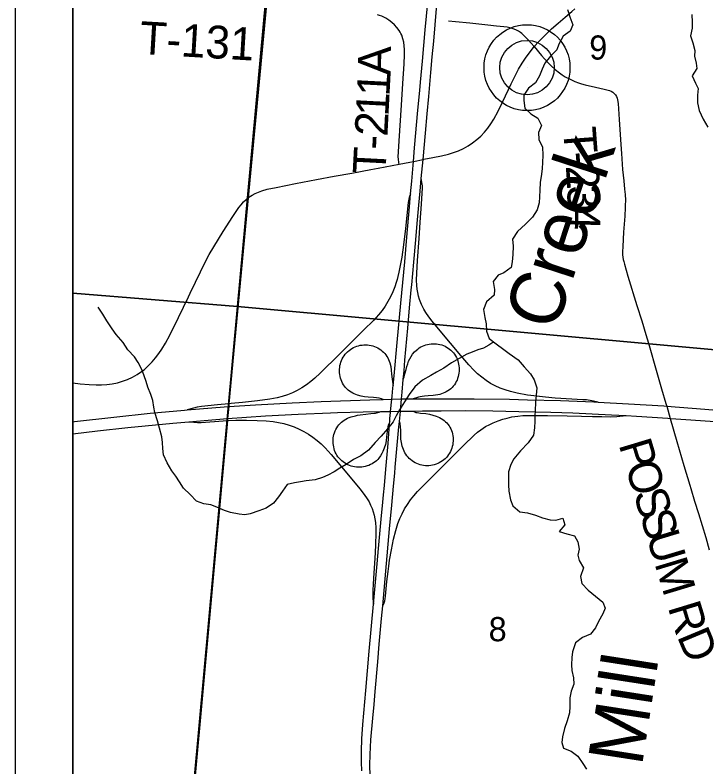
# Model space of a CAD drawing. Extents: x -209 to 4852, y 0 to 905.
# Drawn here: x 57.34 to 81.27, y 222.94 to 248.99 of the extents above; entities that cross this region are included whole.
import ezdxf

# ---------------------------------------------------------------- set-up
doc = ezdxf.new("R2010")
doc.units = 0
for name, color, linetype in [('Default', 7, 'Continuous'), ('GM_X_Corporation', 7, 'Continuous'), ('GM_X_County_Road', 7, 'Continuous'), ('GM_X_County_Road_Text', 7, 'Continuous'), ('GM_X_County_ROW', 7, 'Continuous'), ('GM_X_County_Subdivision', 7, 'Continuous'), ('GM_X_Minor_Lake_Text', 7, 'Continuous'), ('GM_X_Minor_River', 7, 'Continuous'), ('GM_X_Rail_Line', 7, 'Continuous'), ('GM_X_Rail_Line_Text', 7, 'Continuous'), ('GM_X_Section_Text', 7, 'Continuous'), ('GM_X_Township_Road', 7, 'Continuous'), ('GM_X_Township_Road_Text', 7, 'Continuous'), ('GM_X_Township_Subdivision_Text', 7, 'Continuous'), ('SH_Data', 7, 'Continuous')]:
    doc.layers.add(name, color=color, linetype=linetype)

msp = doc.modelspace()

# ---------------------------------------------------------------- linework, layer by layer
at = {"layer": 'Default'}
for points in [[(59.342, 338.559), (195.342, 338.559), (195.342, 202.559), (59.342, 202.559)], [(195.342, 202.559), (195.342, 338.559), (59.342, 338.559), (59.342, 202.559)]]:
    msp.add_lwpolyline(points, close=True, dxfattribs=at)
at = {"layer": 'GM_X_Corporation'}
for points in [[(71.004, 238.842), (71.062, 239.471), (71.078, 239.639), (71.147, 240.425), (71.219, 241.207), (71.269, 241.773), (71.328, 242.408), (71.371, 242.891), (71.411, 243.325), (71.473, 243.989), (71.558, 244.897), (71.614, 245.567), (71.667, 246.166), (71.742, 247.001), (71.792, 247.547), (71.841, 248.083), (71.939, 249.211), (71.966, 249.513), (71.986, 249.75), (72.041, 250.391), (72.091, 250.894), (72.203, 252.114), (72.245, 252.601), (72.295, 253.174)], [(69.35, 222.805), (69.339, 223.114), (69.34, 223.486), (69.355, 223.92), (69.386, 224.415), (69.488, 225.591), (69.611, 226.951), (69.757, 228.587), (69.881, 229.981), (69.927, 230.511), (70.023, 231.531), (70.082, 232.119), (70.103, 232.372), (70.131, 232.695), (70.184, 233.263), (70.259, 234.145), (70.309, 234.825), (70.316, 234.904), (70.325, 235.013), (70.343, 235.217), (70.348, 235.26), (70.39, 235.681), (70.401, 235.789), (70.423, 236.061), (70.434, 236.156), (70.473, 236.492), (70.575, 237.65), (70.7, 239.008), (70.835, 240.445), (70.907, 241.299), (70.999, 242.345), (71.039, 242.801), (71.078, 243.239), (71.131, 243.795), (71.141, 243.922), (71.179, 244.391), (71.294, 245.69), (71.357, 246.376), (71.384, 246.662), (71.453, 247.389), (71.547, 248.473), (71.712, 250.266)], [(70.686, 235.251), (70.687, 235.265), (70.729, 235.691), (70.752, 235.927), (70.788, 236.37), (70.812, 236.663), (70.838, 237.038), (70.94, 238.143), (71.004, 238.842)], [(69.773, 225.108), (69.809, 225.559), (69.901, 226.585), (69.954, 227.194), (70.036, 228.091), (70.075, 228.528), (70.312, 231.195), (70.387, 232.014), (70.447, 232.668), (70.489, 233.116), (70.509, 233.332), (70.634, 234.73), (70.652, 234.911), (70.686, 235.251)], [(71.045, 218.165), (71.025, 218.234), (71.012, 218.276), (70.97, 218.359), (70.735, 218.729), (70.586, 219.002), (70.449, 219.282), (70.323, 219.567), (70.207, 219.856), (70.072, 220.213), (70.009, 220.394), (69.947, 220.611), (69.888, 220.821), (69.829, 221.061), (69.763, 221.407), (69.71, 221.719), (69.671, 222.041), (69.648, 222.34), (69.635, 222.643), (69.625, 223.005), (69.635, 223.379), (69.664, 223.886), (69.735, 224.639), (69.773, 225.108)]]:
    msp.add_lwpolyline(points, dxfattribs=at)
at = {"layer": 'GM_X_County_Road'}
for points in [[(76.478, 249.178), (76.559, 248.928), (76.663, 248.646), (76.563, 248.435), (76.327, 248.254), (76.174, 247.983), (76.104, 247.786), (75.89, 247.56), (75.692, 247.319), (75.6, 247.115), (75.507, 246.888), (75.362, 246.646), (75.126, 246.458), (74.957, 246.217), (74.956, 246.028), (74.999, 245.769), (75.202, 245.563), (75.451, 245.417), (75.57, 245.166), (75.47, 244.924), (75.483, 244.674), (75.602, 244.415), (75.615, 244.135), (75.613, 243.884), (75.597, 243.672), (75.572, 243.475), (75.532, 243.195), (75.515, 242.922), (75.506, 242.687), (75.489, 242.482), (75.427, 242.24), (75.259, 241.984), (75.022, 241.75), (74.74, 241.487), (74.572, 241.223)], [(80.774, 249.01), (80.787, 248.745), (80.785, 248.54), (80.738, 248.267), (80.812, 248.024), (80.878, 247.766), (80.869, 247.569), (80.928, 247.326), (80.949, 247.136), (80.796, 246.887), (80.907, 246.636), (81.004, 246.446), (80.972, 246.211), (80.97, 245.945), (81.036, 245.687), (81.17, 245.383), (81.335, 245.109)], [(74.572, 241.223), (74.593, 240.988), (74.576, 240.692), (74.559, 240.442), (74.527, 240.245), (74.268, 240.057), (74.078, 239.975), (73.903, 239.764), (73.946, 239.484), (73.937, 239.286), (73.663, 239.053), (73.563, 238.789), (73.613, 238.508), (73.657, 238.295), (73.663, 238.045), (73.759, 237.786), (74.008, 237.603), (74.263, 237.404), (74.459, 237.266), (74.76, 237.051), (74.97, 236.807), (75.188, 236.563), (75.322, 236.357), (75.411, 236.076), (75.394, 235.818), (75.362, 235.568), (75.352, 235.295), (75.343, 235.106), (75.342, 234.916), (75.333, 234.696), (75.3, 234.431), (75.109, 234.175), (74.842, 233.889), (74.613, 233.617), (74.506, 233.421), (74.436, 233.171), (74.427, 232.906), (74.433, 232.716), (74.446, 232.496), (74.504, 232.2), (74.586, 231.987), (74.827, 231.781), (75.084, 231.748), (75.363, 231.663), (75.612, 231.57), (75.869, 231.508), (76.065, 231.491), (76.316, 231.565), (76.382, 231.329), (76.183, 231.103), (76.455, 231.018), (76.712, 230.948), (76.831, 230.742), (76.882, 230.484), (76.836, 230.28), (76.879, 230.09), (77.029, 229.838), (76.928, 229.543), (76.964, 229.301), (77.19, 229.071), (77.445, 228.857), (77.701, 228.651), (77.783, 228.445), (77.698, 228.249), (77.545, 227.985), (77.445, 227.758), (77.269, 227.547), (76.996, 227.427), (76.752, 227.24), (76.652, 226.93), (76.62, 226.733), (76.61, 226.482), (76.624, 226.285), (76.683, 226.027), (76.689, 225.807), (76.604, 225.573), (76.556, 225.338), (76.554, 225.042), (76.545, 224.822), (76.467, 224.542), (76.367, 224.278), (76.297, 223.99), (76.273, 223.793), (76.332, 223.596), (76.603, 223.487), (76.829, 223.319), (77.001, 223.067), (77.136, 222.869)], [(73.922, 237.666), (73.75, 237.551), (73.56, 237.447), (73.371, 237.387), (73.173, 237.313), (72.984, 237.246), (72.718, 237.089), (72.452, 236.947), (72.193, 236.759), (71.942, 236.617), (71.737, 236.505), (71.456, 236.347), (71.19, 236.114), (70.991, 235.85), (70.83, 235.586), (70.654, 235.315), (70.539, 235.103), (70.439, 234.899), (70.241, 234.658), (70.019, 234.402), (69.813, 234.183), (69.584, 233.912), (69.318, 233.717), (69.067, 233.59), (68.809, 233.425), (68.589, 233.29), (68.391, 233.163), (68.178, 233.05), (67.988, 232.968), (67.731, 232.887), (67.428, 232.851), (67.223, 232.822), (67.019, 232.786), (66.769, 232.727), (66.6, 232.493), (66.47, 232.297), (66.287, 232.079), (66.036, 231.906), (65.786, 231.817), (65.49, 231.713), (65.301, 231.676), (65.104, 231.701), (64.802, 231.756), (64.598, 231.826), (64.334, 231.941), (64.123, 232.019), (63.881, 232.058), (63.624, 232.151), (63.407, 232.38), (63.174, 232.602), (63.039, 232.815), (62.912, 233.013), (62.777, 233.204), (62.605, 233.478), (62.486, 233.752), (62.458, 233.972), (62.444, 234.184), (62.423, 234.374), (62.35, 234.678), (62.276, 234.936), (62.187, 235.218), (62.151, 235.407), (62.115, 235.635), (62.041, 235.84), (61.937, 236.099), (61.885, 236.297), (61.818, 236.487), (61.729, 236.715), (61.61, 236.958), (61.483, 237.149), (61.243, 237.393), (61.086, 237.645), (60.846, 237.919), (60.703, 238.117), (60.524, 238.392), (60.382, 238.628), (60.217, 238.872)]]:
    msp.add_lwpolyline(points, dxfattribs=at)
at = {"layer": 'GM_X_County_Road_Text'}
for points in [[(75.323, 247.898), (75.482, 248.074), (75.655, 248.251), (75.923, 248.508), (76.155, 248.714), (76.389, 248.917), (76.626, 249.117), (76.728, 249.204)], [(70.641, 243.825), (70.833, 243.861), (71.016, 243.897), (71.141, 243.922), (71.473, 243.989), (71.503, 243.995), (71.808, 244.053), (72.112, 244.113), (72.352, 244.173), (72.53, 244.227), (72.703, 244.291), (72.872, 244.367), (73.034, 244.456), (73.187, 244.559), (73.332, 244.674), (73.469, 244.799), (73.596, 244.933), (73.714, 245.076), (73.822, 245.226), (73.92, 245.384), (74.067, 245.656), (74.23, 245.991), (74.519, 246.611), (74.66, 246.889), (74.779, 247.112), (74.905, 247.321), (75.041, 247.531), (75.191, 247.731), (75.323, 247.898)], [(69.658, 243.641), (69.918, 243.69), (70.641, 243.825)], [(65.413, 242.656), (65.444, 242.682), (65.55, 242.75), (65.661, 242.809), (65.776, 242.86), (65.894, 242.903), (66.075, 242.953), (66.379, 243.019), (67.049, 243.152), (67.782, 243.291), (68.392, 243.408), (69.003, 243.517), (69.658, 243.641)], [(63.346, 239.23), (63.405, 239.353), (63.951, 240.47), (64.067, 240.69), (64.224, 240.959), (64.552, 241.487), (64.888, 242.011), (65.097, 242.32), (65.173, 242.42), (65.256, 242.514), (65.346, 242.603), (65.411, 242.655), (65.413, 242.656)], [(59.342, 236.251), (59.599, 236.217), (59.907, 236.187), (60.155, 236.175), (60.34, 236.177), (60.525, 236.189), (60.708, 236.214), (60.889, 236.253), (61.067, 236.305), (61.24, 236.37), (61.407, 236.449), (61.569, 236.539), (61.723, 236.642), (61.82, 236.717), (61.957, 236.842), (62.086, 236.974), (62.208, 237.114), (62.32, 237.261), (62.425, 237.415), (62.553, 237.626), (62.697, 237.9), (63.001, 238.513), (63.346, 239.23)]]:
    msp.add_lwpolyline(points, dxfattribs=at)
at = {"layer": 'GM_X_County_ROW'}
for points in [[(70.641, 243.825), (70.636, 243.868), (70.618, 244.012), (70.614, 244.07), (70.647, 244.628), (70.729, 245.869), (70.774, 246.614), (70.82, 247.297), (70.834, 247.608), (70.832, 247.796), (70.822, 247.921), (70.802, 248.046), (70.772, 248.168), (70.731, 248.288), (70.706, 248.346), (70.677, 248.402), (70.644, 248.456), (70.569, 248.558), (70.484, 248.652), (70.39, 248.736), (70.29, 248.813), (70.183, 248.879), (70.108, 248.92), (70.04, 248.949), (69.964, 248.976), (69.899, 248.995)], [(75.323, 247.898), (75.107, 248.126), (74.983, 248.263), (74.893, 248.349), (74.846, 248.388), (74.778, 248.435), (74.686, 248.482), (74.593, 248.515), (74.481, 248.544), (74.387, 248.565), (74.264, 248.585), (74.018, 248.61), (73.71, 248.645), (73.093, 248.703), (72.6, 248.755), (72.353, 248.774)], [(75.323, 247.898), (75.576, 247.594), (75.782, 247.362), (75.91, 247.228), (76.046, 247.102), (76.191, 246.987), (76.292, 246.916), (76.397, 246.852), (76.561, 246.766), (76.731, 246.691), (76.851, 246.647), (76.962, 246.611), (77.082, 246.576), (77.445, 246.495), (77.746, 246.422), (77.925, 246.372), (77.985, 246.349), (78.041, 246.318), (78.094, 246.275), (78.135, 246.228), (78.168, 246.172), (78.192, 246.112), (78.207, 246.05), (78.224, 245.924), (78.263, 245.366), (78.321, 244.501), (78.34, 244.191), (78.382, 243.634), (78.4, 243.441), (78.419, 243.244), (78.453, 242.955), (78.469, 242.768), (78.477, 242.581), (78.476, 242.394), (78.471, 242.269), (78.464, 242.083), (78.461, 242.02), (78.413, 241.463), (78.384, 240.968), (78.379, 240.783), (78.383, 240.679), (78.389, 240.607), (78.405, 240.518), (78.42, 240.456), (78.444, 240.359), (78.566, 239.942), (78.876, 238.932), (79.042, 238.397), (79.185, 237.921), (79.273, 237.623), (79.566, 236.608), (79.731, 236.044)], [(79.731, 236.044), (79.881, 235.535), (79.908, 235.443), (80.03, 235.019), (80.26, 234.22), (80.505, 233.386), (80.708, 232.699), (80.74, 232.593)], [(80.74, 232.593), (80.875, 232.146), (81.007, 231.718), (81.259, 230.886), (81.383, 230.469)]]:
    msp.add_lwpolyline(points, dxfattribs=at)
at = {"layer": 'GM_X_County_Subdivision'}
msp.add_line((75.071, 247.168), (75.071, 247.168), dxfattribs=at)
at = {"layer": 'GM_X_Minor_Lake_Text'}
msp.add_lwpolyline([(59.342, 300.452), (59.342, 264.57), (60.024, 264.424), (61.555, 264.195), (62.287, 263.967), (63.11, 263.99), (64.161, 263.807), (64.71, 263.579), (65.099, 263.51), (66.173, 263.396), (66.47, 263.327), (67.328, 262.997), (67.133, 261.449), (67.026, 260.458), (66.046, 249.36), (65.411, 242.655), (64.751, 235.526), (64.741, 235.424), (64.703, 235.009), (64.697, 234.939), (62.039, 205.774), (61.776, 202.559), (195.342, 202.559)], dxfattribs=at)
msp.add_lwpolyline([(59.342, 264.57), (59.342, 202.559), (61.776, 202.559), (62.039, 205.774), (64.697, 234.939), (64.703, 235.009), (64.741, 235.424), (64.751, 235.526), (65.411, 242.655), (66.046, 249.36), (67.026, 260.458), (67.133, 261.449), (67.328, 262.997), (66.47, 263.327), (66.173, 263.396), (65.099, 263.51), (64.71, 263.579), (64.161, 263.807), (63.11, 263.99), (62.287, 263.967), (61.555, 264.195), (60.024, 264.424)], close=True, dxfattribs=at)
at = {"layer": 'GM_X_Minor_River'}
for points in [[(59.342, 259.84), (59.342, 239.357), (65.048, 238.898), (66.919, 259.238)], [(66.919, 259.238), (87.119, 257.725), (84.904, 237.096), (65.048, 238.898)], [(59.342, 239.357), (59.342, 219.113), (63.212, 218.824), (65.048, 238.898)], [(65.048, 238.898), (84.904, 237.096), (83.068, 217.043), (63.212, 218.824)]]:
    msp.add_lwpolyline(points, close=True, dxfattribs=at)
at = {"layer": 'GM_X_Rail_Line'}
for points in [[(77.536, 235.579), (77.32, 235.628), (77.132, 235.657), (77.008, 235.664), (76.042, 235.719), (75.711, 235.755), (75.208, 235.81), (75.092, 235.828), (74.736, 235.892), (74.495, 235.949), (74.317, 236.002), (74.143, 236.067), (73.974, 236.144), (73.81, 236.232), (73.653, 236.331), (73.503, 236.441), (73.361, 236.561), (73.227, 236.689), (73.058, 236.87), (72.775, 237.199), (72.059, 238.054), (71.783, 238.389), (71.67, 238.536), (71.566, 238.69), (71.503, 238.797), (71.421, 238.964), (71.354, 239.137), (71.317, 239.255), (71.288, 239.376), (71.267, 239.498), (71.254, 239.621), (71.248, 239.806), (71.254, 240.054), (71.278, 240.487), (71.331, 241.247), (71.373, 241.82), (71.418, 242.444), (71.454, 243.001), (71.45, 243.07), (71.442, 243.13), (71.411, 243.325)], [(71.039, 242.801), (71, 242.704), (70.988, 242.668), (70.976, 242.614), (70.957, 242.491), (70.866, 241.591), (70.796, 241.035), (70.731, 240.604), (70.679, 240.317), (70.63, 240.08), (70.598, 239.932), (70.574, 239.83), (70.541, 239.722), (70.492, 239.574), (70.424, 239.4), (70.345, 239.23), (70.257, 239.065), (70.159, 238.907), (70.05, 238.755), (69.933, 238.61), (69.765, 238.426), (69.412, 238.074), (68.573, 237.24), (67.907, 236.584), (67.724, 236.415), (67.581, 236.295), (67.432, 236.182), (67.277, 236.078), (67.116, 235.985), (66.948, 235.903), (66.774, 235.834), (66.596, 235.778), (66.415, 235.734), (66.17, 235.689), (65.738, 235.63), (65.421, 235.594), (65.218, 235.573), (64.829, 235.534), (64.751, 235.526), (64.349, 235.486), (63.797, 235.43), (63.654, 235.406), (63.521, 235.373), (63.302, 235.312)], [(70.093, 235.673), (70.028, 235.691), (69.949, 235.714), (69.864, 235.73), (69.759, 235.738), (69.573, 235.748), (69.449, 235.764), (69.327, 235.788), (69.207, 235.823), (69.091, 235.868), (69.035, 235.895), (68.981, 235.926), (68.929, 235.961), (68.88, 235.999), (68.833, 236.04), (68.79, 236.085), (68.75, 236.134), (68.715, 236.185), (68.684, 236.239), (68.658, 236.295), (68.635, 236.353), (68.616, 236.413), (68.601, 236.473), (68.59, 236.535), (68.583, 236.597), (68.58, 236.659), (68.58, 236.721), (68.585, 236.783), (68.593, 236.845), (68.607, 236.906), (68.624, 236.966), (68.646, 237.024), (68.672, 237.08), (68.702, 237.135), (68.737, 237.187), (68.774, 237.237), (68.815, 237.283), (68.86, 237.327), (68.907, 237.368), (68.956, 237.406), (69.009, 237.44), (69.063, 237.47), (69.12, 237.496), (69.178, 237.518), (69.238, 237.536), (69.298, 237.55), (69.36, 237.56), (69.422, 237.566), (69.484, 237.567), (69.546, 237.564), (69.608, 237.557), (69.669, 237.545), (69.729, 237.528), (69.788, 237.509), (69.846, 237.485), (69.902, 237.457), (69.956, 237.426), (70.007, 237.391), (70.056, 237.352), (70.102, 237.31), (70.144, 237.264), (70.183, 237.215), (70.218, 237.164), (70.25, 237.11), (70.278, 237.055), (70.323, 236.938), (70.354, 236.818), (70.372, 236.694), (70.381, 236.547), (70.397, 236.381), (70.412, 236.287), (70.434, 236.156)], [(70.788, 236.37), (70.82, 236.462), (70.833, 236.506), (70.846, 236.558), (70.881, 236.712), (70.913, 236.819), (70.939, 236.911), (70.973, 237), (71.011, 237.086), (71.054, 237.162), (71.11, 237.243), (71.175, 237.319), (71.242, 237.382), (71.291, 237.421), (71.34, 237.459), (71.393, 237.492), (71.448, 237.521), (71.505, 237.544), (71.564, 237.564), (71.625, 237.579), (71.686, 237.591), (71.748, 237.599), (71.81, 237.602), (71.872, 237.602), (71.934, 237.598), (71.996, 237.59), (72.057, 237.578), (72.117, 237.562), (72.175, 237.541), (72.233, 237.516), (72.288, 237.488), (72.34, 237.455), (72.39, 237.418), (72.438, 237.377), (72.482, 237.334), (72.523, 237.287), (72.561, 237.237), (72.595, 237.185), (72.624, 237.131), (72.649, 237.077), (72.672, 237.016), (72.69, 236.956), (72.704, 236.896), (72.714, 236.834), (72.719, 236.772), (72.721, 236.71), (72.718, 236.648), (72.712, 236.586), (72.701, 236.525), (72.687, 236.464), (72.669, 236.405), (72.647, 236.347), (72.621, 236.29), (72.59, 236.236), (72.556, 236.184), (72.518, 236.135), (72.476, 236.089), (72.43, 236.047), (72.382, 236.008), (72.331, 235.973), (72.277, 235.941), (72.222, 235.913), (72.17, 235.891), (72.106, 235.867), (72.053, 235.849), (71.984, 235.832), (71.817, 235.808), (71.648, 235.795), (71.522, 235.783), (71.436, 235.774), (71.374, 235.766), (71.316, 235.752), (71.247, 235.732), (71.128, 235.694)], [(70.316, 234.904), (70.268, 234.779), (70.25, 234.72), (70.236, 234.651), (70.211, 234.374), (70.194, 234.243), (70.166, 234.111), (70.129, 233.983), (70.083, 233.87), (70.044, 233.796), (69.998, 233.725), (69.942, 233.644), (69.901, 233.597), (69.856, 233.553), (69.808, 233.513), (69.757, 233.477), (69.704, 233.445), (69.648, 233.416), (69.591, 233.39), (69.532, 233.369), (69.472, 233.351), (69.411, 233.337), (69.349, 233.328), (69.287, 233.323), (69.224, 233.323), (69.162, 233.327), (69.1, 233.335), (69.038, 233.348), (68.978, 233.365), (68.919, 233.386), (68.862, 233.412), (68.807, 233.441), (68.754, 233.474), (68.702, 233.511), (68.654, 233.55), (68.608, 233.593), (68.566, 233.639), (68.526, 233.687), (68.491, 233.739), (68.459, 233.793), (68.432, 233.849), (68.409, 233.907), (68.39, 233.967), (68.376, 234.028), (68.365, 234.09), (68.358, 234.152), (68.355, 234.215), (68.357, 234.277), (68.362, 234.34), (68.372, 234.402), (68.385, 234.463), (68.404, 234.522), (68.426, 234.581), (68.453, 234.637), (68.484, 234.692), (68.519, 234.744), (68.558, 234.793), (68.6, 234.839), (68.645, 234.882), (68.693, 234.923), (68.744, 234.959), (68.797, 234.992), (68.853, 235.021), (68.91, 235.047), (68.984, 235.071), (69.131, 235.11), (69.204, 235.125), (69.291, 235.141), (69.493, 235.168), (69.667, 235.183), (69.785, 235.193), (69.819, 235.197), (69.857, 235.205), (69.95, 235.235), (70.013, 235.255)], [(71.115, 235.271), (71.178, 235.241), (71.218, 235.227), (71.262, 235.217), (71.382, 235.198), (71.568, 235.182), (71.691, 235.162), (71.812, 235.134), (71.931, 235.094), (72.045, 235.044), (72.099, 235.014), (72.152, 234.981), (72.202, 234.944), (72.249, 234.904), (72.294, 234.86), (72.334, 234.813), (72.371, 234.763), (72.404, 234.71), (72.432, 234.655), (72.457, 234.598), (72.476, 234.538), (72.492, 234.478), (72.503, 234.417), (72.511, 234.355), (72.514, 234.293), (72.513, 234.231), (72.508, 234.168), (72.499, 234.107), (72.485, 234.046), (72.468, 233.986), (72.446, 233.928), (72.42, 233.871), (72.391, 233.816), (72.357, 233.764), (72.32, 233.714), (72.28, 233.667), (72.236, 233.622), (72.189, 233.581), (72.14, 233.543), (72.088, 233.508), (72.034, 233.477), (71.978, 233.45), (71.92, 233.427), (71.861, 233.408), (71.8, 233.393), (71.739, 233.383), (71.677, 233.377), (71.615, 233.376), (71.553, 233.379), (71.491, 233.386), (71.43, 233.397), (71.369, 233.413), (71.31, 233.433), (71.252, 233.456), (71.196, 233.484), (71.142, 233.515), (71.091, 233.55), (71.042, 233.588), (70.996, 233.63), (70.954, 233.676), (70.914, 233.724), (70.878, 233.775), (70.846, 233.828), (70.817, 233.883), (70.769, 233.998), (70.749, 234.057), (70.721, 234.178), (70.705, 234.302), (70.698, 234.426), (70.701, 234.575), (70.686, 234.763), (70.681, 234.806), (70.674, 234.846), (70.652, 234.911)], [(63.358, 234.904), (63.533, 234.884), (63.655, 234.877), (63.789, 234.879), (64.55, 234.933), (64.697, 234.939), (64.984, 234.953), (65.356, 234.958), (65.729, 234.95), (66.039, 234.932), (66.286, 234.906), (66.47, 234.876), (66.652, 234.836), (66.831, 234.785), (67.006, 234.723), (67.177, 234.65), (67.344, 234.567), (67.505, 234.474), (67.66, 234.37), (67.808, 234.257), (67.948, 234.135), (68.08, 234.003), (68.287, 233.772), (69.005, 232.917), (69.282, 232.581), (69.433, 232.384), (69.537, 232.23), (69.6, 232.123), (69.656, 232.012), (69.704, 231.897), (69.746, 231.78), (69.78, 231.661), (69.806, 231.54), (69.825, 231.417), (69.839, 231.232), (69.841, 231.045), (69.825, 230.653), (69.808, 230.366), (69.787, 230.007), (69.756, 229.48), (69.732, 229.073), (69.728, 228.872), (69.735, 228.773), (69.757, 228.587)], [(70.075, 228.528), (70.122, 228.634), (70.144, 228.696), (70.162, 228.764), (70.171, 228.857), (70.22, 229.363), (70.26, 229.711), (70.282, 229.904), (70.31, 230.103), (70.374, 230.47), (70.451, 230.835), (70.526, 231.136), (70.599, 231.374), (70.665, 231.548), (70.743, 231.717), (70.832, 231.881), (70.931, 232.039), (71.039, 232.191), (71.151, 232.335), (71.283, 232.486), (71.714, 232.92), (72.976, 234.183), (73.134, 234.337), (73.236, 234.433), (73.361, 234.538), (73.473, 234.624), (73.637, 234.732), (73.779, 234.808), (73.894, 234.86), (74.074, 234.936), (74.232, 234.988), (74.38, 235.031), (74.548, 235.067), (74.755, 235.1), (74.923, 235.113), (75.183, 235.123), (75.78, 235.115), (76.46, 235.101), (76.956, 235.093), (77.344, 235.086), (77.657, 235.08), (77.952, 235.075), (78.179, 235.086), (78.509, 235.116)]]:
    msp.add_lwpolyline(points, dxfattribs=at)
at = {"layer": 'GM_X_Rail_Line_Text'}
for points in [[(59.342, 234.903), (59.404, 234.911), (60.763, 235.062), (62.017, 235.194), (63.213, 235.305), (63.302, 235.312), (64.579, 235.413), (64.741, 235.424), (65.67, 235.486), (66.939, 235.555), (67.947, 235.599), (69.625, 235.66), (70.093, 235.673), (70.39, 235.681), (70.729, 235.691), (71.128, 235.694), (71.172, 235.694), (71.645, 235.694), (72.472, 235.701), (73.24, 235.698), (74.46, 235.68), (75.092, 235.663), (76.236, 235.632), (77.39, 235.587), (77.536, 235.579), (78.585, 235.524), (79.805, 235.451), (79.908, 235.443), (81.229, 235.339), (82.343, 235.245)], [(59.342, 234.486), (60.196, 234.588), (61.246, 234.701), (62.804, 234.858), (63.358, 234.904), (63.889, 234.95), (64.703, 235.009), (65.358, 235.058), (66.015, 235.102), (67.148, 235.162), (68.272, 235.211)], [(68.272, 235.211), (68.513, 235.222), (69.394, 235.246), (70.013, 235.255), (70.072, 235.256)], [(70.072, 235.256), (70.348, 235.26), (70.687, 235.265), (70.981, 235.269), (71.056, 235.27)], [(71.056, 235.27), (71.115, 235.271), (71.455, 235.276)], [(71.455, 235.276), (72.099, 235.284), (72.945, 235.29), (73.886, 235.282), (74.783, 235.262), (75.9, 235.234), (76.653, 235.21), (77.998, 235.143), (78.509, 235.116), (78.867, 235.097), (79.943, 235.026), (80.03, 235.019), (80.046, 235.018)], [(80.046, 235.018), (80.748, 234.966), (81.581, 234.905), (83.214, 234.745), (84.223, 234.645), (85.516, 234.497), (86.73, 234.341), (87.959, 234.173), (89.368, 233.965), (90.349, 233.809), (91.506, 233.624), (92.002, 233.544), (92.742, 233.422)]]:
    msp.add_lwpolyline(points, dxfattribs=at)
at = {"layer": 'GM_X_Township_Subdivision_Text'}
for radius in [1.488, 0.943]:
    msp.add_circle((75.071, 247.168), radius, dxfattribs=at)
at = {"layer": 'SH_Data'}
msp.add_line((57.342, 340.559), (57.342, 200.559), dxfattribs=at)

# ---------------------------------------------------------------- texts
at = {"layer": 'GM_X_Section_Text'}
for s, height, rotation, p in [('Creek', 1.8935, 71.9853, (76.061, 237.984)), ('Mill', 1.8934, 81.1767, (79.049, 222.937))]:
    msp.add_text(s, height=height, rotation=rotation, dxfattribs=at).set_placement(p)
at = {"layer": 'GM_X_Township_Road'}
for s, height, rotation, p in [('T-131', 1.1364, 356.6344, (61.635, 247.644)), ('A', 1.136, 89.0887, (70.344, 246.894)), ('1', 1.136, 87.0482, (70.307, 246.156)), ('1', 1.136, 87.0411, (70.271, 245.463)), ('2', 1.136, 87.0408, (70.236, 244.769)), ('T', 1.136, 274.354, (76.316, 245.075)), ('-', 1.136, 87.0408, (70.212, 244.307)), ('T', 1.136, 87.0408, (70.168, 243.46)), ('-', 1.136, 274.1799, (76.38, 244.229)), ('2', 1.136, 273.6296, (76.414, 243.766)), ('3', 1.136, 272.2851, (76.458, 243.074)), ('4', 1.136, 268.803, (76.486, 242.393)), ('P', 1.136, 286.7932, (78.238, 234.116)), ('O', 1.136, 286.7921, (78.46, 233.382)), ('S', 1.136, 286.7953, (78.748, 232.425)), ('S', 1.136, 286.7932, (78.97, 231.691)), ('U', 1.136, 286.7921, (79.192, 230.957)), ('M', 1.136, 286.8031, (79.48, 229.999)), ('R', 1.136, 286.997, (79.94, 228.48)), ('D', 1.136, 292.6768, (80.254, 227.471))]:
    msp.add_text(s, height=height, rotation=rotation, dxfattribs=at).set_placement(p)
at = {"layer": 'GM_X_Township_Road_Text'}
for s, p in [('9', (77.227, 247.447)), ('8', (73.744, 227.298))]:
    msp.add_text(s, height=0.837, rotation=0, dxfattribs=at).set_placement(p)

doc.saveas('drawing.dxf')
